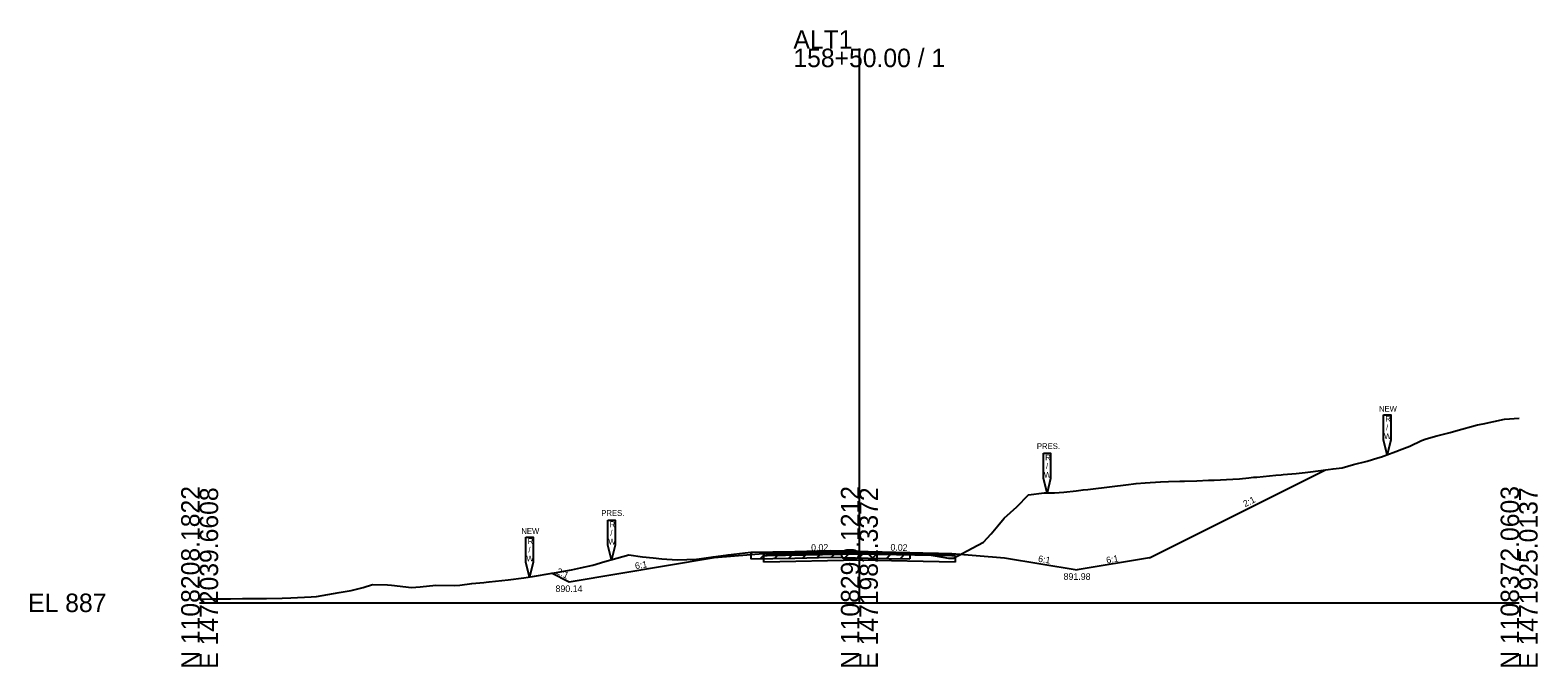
# Model space of a CAD drawing. Extents: x -26 to 2203, y -10 to 19568.
# Drawn here: x 974.3 to 1202.8, y 490.3 to 586.7 of the extents above; entities that cross this region are included whole.
import ezdxf

# ---------------------------------------------------------------- set-up
doc = ezdxf.new("R2010")
doc.units = 0
for name, color, linetype in [('RD_GPK_XS_Cell', 7, 'Continuous'), ('RD_XS_Base', 7, 'Continuous'), ('RD_XS_ExGround', 7, 'Continuous'), ('RD_XS_ExPaveRet', 7, 'Continuous'), ('RD_XS_ExRW', 7, 'Continuous'), ('RD_XS_Greenside', 7, 'Continuous'), ('RD_XS_NewRW', 7, 'Continuous'), ('RD_XS_Pave', 7, 'Continuous'), ('RD_XS_TieSlope', 7, 'Continuous'), ('RD_XS_TX_Slope', 7, 'Continuous')]:
    doc.layers.add(name, color=color, linetype=linetype)

msp = doc.modelspace()

# ---------------------------------------------------------------- linework, layer by layer
at = {"layer": 'RD_GPK_XS_Cell'}
for p, q in [((1100, 500), (1100, 583.93)), ((1000, 500), (1100, 500)), ((1100, 500), (1200, 500))]:
    msp.add_line(p, q, dxfattribs=at)
at = {"layer": 'RD_XS_Base'}
for points in [[(1085.5, 507.15), (1086, 507.16), (1100, 507.44), (1114, 507.16), (1114.5, 507.15)], [(1085.5, 506.15), (1085.5, 507.15)], [(1114.5, 506.15), (1100, 506.44), (1085.5, 506.15)], [(1114.5, 507.15), (1114.5, 506.15)]]:
    msp.add_lwpolyline(points, dxfattribs=at)
at = {"layer": 'RD_XS_ExGround'}
msp.add_lwpolyline([(1000, 500.54), (1002.02, 500.59), (1002.83, 500.6), (1004.65, 500.6), (1006.49, 500.63), (1007.26, 500.63), (1010.15, 500.66), (1012.49, 500.72), (1013.81, 500.76), (1016.89, 500.9), (1017.73, 500.97), (1021.13, 501.54), (1022.96, 501.85), (1024.8, 502.31), (1026.19, 502.75), (1028.46, 502.71), (1029.08, 502.65), (1032.12, 502.33), (1033.43, 502.43), (1035.78, 502.65), (1038.66, 502.64), (1039.44, 502.67), (1041.27, 502.92), (1043.1, 503.09), (1043.43, 503.13), (1043.89, 503.2), (1046.76, 503.49), (1049.13, 503.78), (1050.43, 504.01), (1053.45, 504.51), (1054.36, 504.66), (1056.35, 505), (1057.75, 505.28), (1059.59, 505.71), (1061.41, 506.25), (1065.07, 507.26), (1067.12, 506.99), (1068.73, 506.82), (1070.06, 506.67), (1072.39, 506.49), (1075.29, 506.63), (1076.05, 506.7), (1077.83, 506.96), (1080.09, 507.27), (1083.57, 507.65), (1090.21, 507.78), (1095.64, 507.9), (1100, 507.8), (1101.35, 507.77), (1107.66, 507.64), (1109.78, 507.42), (1110.3, 507.33), (1113.51, 506.75), (1114.25, 506.75), (1117.11, 508.28), (1118.82, 509.21), (1119.99, 510.44), (1120.98, 511.67), (1121.97, 512.84), (1123.85, 514.56), (1125.63, 516.36), (1128.02, 516.64), (1129.6, 516.67), (1130.97, 516.75), (1132.86, 516.96), (1133.9, 517.1), (1134.63, 517.16), (1138.3, 517.61), (1140.37, 517.85), (1141.96, 518.07), (1143.33, 518.19), (1145.62, 518.31), (1146.83, 518.38), (1148.56, 518.43), (1149.28, 518.45), (1151.14, 518.5), (1152.94, 518.56), (1153.8, 518.6), (1156.6, 518.73), (1157.6, 518.8), (1159.03, 518.94), (1159.75, 519.01), (1160.26, 519.04), (1163.14, 519.31), (1163.92, 519.38), (1164.26, 519.41), (1166.22, 519.6), (1167.59, 519.74), (1168.37, 519.82), (1169.56, 519.98), (1171.83, 520.31), (1173.16, 520.47), (1174.9, 520.94), (1176.99, 521.47), (1178.57, 521.94), (1179.14, 522.12), (1179.96, 522.43), (1181.3, 522.91), (1182.23, 523.27), (1183.45, 523.73), (1185.2, 524.57), (1185.89, 524.84), (1187.51, 525.27), (1189.55, 525.79), (1190.42, 526.03), (1193.67, 526.94), (1194.53, 527.09), (1197.81, 527.8), (1200, 527.98)], dxfattribs=at)
at = {"layer": 'RD_XS_ExPaveRet'}
for p, q in [((1083.57, 507.41), (1083.81, 507.66)), ((1083.57, 507.65), (1083.57, 506.65)), ((1084.96, 506.68), (1085.98, 507.7)), ((1087.12, 506.72), (1088.14, 507.74)), ((1089.29, 506.76), (1090.31, 507.79)), ((1091.45, 506.81), (1092.48, 507.83)), ((1093.62, 506.86), (1094.64, 507.88)), ((1095.78, 506.9), (1096.76, 507.87)), ((1097.86, 506.85), (1098.84, 507.83)), ((1099.93, 506.8), (1100.91, 507.78)), ((1102.01, 506.76), (1102.99, 507.74)), ((1104.09, 506.71), (1105.07, 507.69)), ((1106.17, 506.67), (1107.15, 507.65)), ((1107.66, 507.64), (1107.66, 506.64))]:
    msp.add_line(p, q, dxfattribs=at)
msp.add_lwpolyline([(1083.57, 506.65), (1090.23, 506.78), (1095.64, 506.9), (1101.33, 506.77), (1107.66, 506.64)], dxfattribs=at)
at = {"layer": 'RD_XS_ExRW'}
for points in [[(1127.9, 522.66), (1128.99, 522.66), (1128.99, 518.83), (1128.44, 516.65), (1127.9, 518.83)], [(1061.87, 512.54), (1062.96, 512.54), (1062.96, 508.71), (1062.42, 506.53), (1061.87, 508.71)]]:
    msp.add_lwpolyline(points, close=True, dxfattribs=at)
at = {"layer": 'RD_XS_Greenside'}
for points in [[(1086, 507.48), (1078, 506.81)], [(1114, 507.48), (1122, 506.81)], [(1078, 506.81), (1056, 503.14)], [(1122, 506.81), (1133, 504.98)], [(1144, 506.81), (1133, 504.98)]]:
    msp.add_lwpolyline(points, dxfattribs=at)
at = {"layer": 'RD_XS_NewRW'}
for points in [[(1179.45, 528.47), (1180.55, 528.47), (1180.55, 524.64), (1180, 522.45), (1179.45, 524.64)], [(1049.45, 509.95), (1050.55, 509.95), (1050.55, 506.12), (1050, 503.94), (1049.45, 506.12)]]:
    msp.add_lwpolyline(points, close=True, dxfattribs=at)
at = {"layer": 'RD_XS_Pave'}
for points in [[(1086, 507.48), (1088, 507.52), (1100, 507.76), (1112, 507.52), (1114, 507.48)], [(1086, 507.32), (1100, 507.6), (1114, 507.32)], [(1114, 507.32), (1100, 507.6), (1086, 507.32)], [(1086, 507.32), (1086, 507.48)], [(1114, 507.16), (1100, 507.44), (1086, 507.16)], [(1114, 507.48), (1114, 507.32)], [(1086, 507.16), (1086, 507.32)], [(1114, 507.32), (1114, 507.16)]]:
    msp.add_lwpolyline(points, dxfattribs=at)
at = {"layer": 'RD_XS_TieSlope'}
for points in [[(1144, 506.81), (1170.64, 520.13)], [(1056, 503.14), (1053.31, 504.49)]]:
    msp.add_lwpolyline(points, dxfattribs=at)

# ---------------------------------------------------------------- texts
at = {"layer": 'RD_GPK_XS_Cell'}
for s, p in [('ALT1', (1090, 583.93)), ('158+50.00 / 1', (1090, 581.13)), ('EL 887', (974, 498.6))]:
    msp.add_text(s, height=2.8, dxfattribs=at).set_placement(p)
for s, p in [('N 1108208.1822', (1000, 490)), ('E 1472039.6608', (1002.8, 490)), ('N 1108290.1212', (1100, 490)), ('E 1471982.3372', (1102.8, 490)), ('N 1108372.0603', (1200, 490)), ('E 1471925.0137', (1202.8, 490))]:
    msp.add_text(s, height=2.8, rotation=90, dxfattribs=at).set_placement(p)
at = {"layer": 'RD_XS_ExRW'}
for s, p in [('PRES.', (1126.9, 523.29)), ('R', (1128.16, 521.57)), ('/', (1128.28, 520.26)), ('W', (1127.97, 518.95)), ('PRES.', (1060.87, 513.17)), ('R', (1062.13, 511.45)), ('W', (1061.95, 508.83)), ('/', (1062.25, 510.14))]:
    msp.add_text(s, height=0.875, dxfattribs=at).set_placement(p)
at = {"layer": 'RD_XS_NewRW'}
for s, p in [('NEW', (1178.75, 528.95)), ('R', (1179.71, 527.43)), ('W', (1179.53, 524.8)), ('/', (1179.83, 526.12)), ('NEW', (1048.75, 510.44)), ('R', (1049.71, 508.91)), ('/', (1049.83, 507.6)), ('W', (1049.53, 506.29))]:
    msp.add_text(s, height=0.875, dxfattribs=at).set_placement(p)
at = {"layer": 'RD_XS_TX_Slope'}
for s, rotation, p in [('2:1', 26.5651, (1158.47, 514.47)), ('0.02', 1.1458, (1092.69, 507.86)), ('0.02', 358.8542, (1104.7, 507.91)), ('2:1', 333.4349, (1053.97, 504.44)), ('6:1', 9.4642, (1066.07, 505.08)), ('6:1', 350.5358, (1127.04, 506.23)), ('6:1', 10.416, (1137.51, 505.94))]:
    msp.add_text(s, height=1, rotation=rotation, dxfattribs=at).set_placement(p)
for s, p in [('891.98', (1130.95, 503.48)), ('890.14', (1053.94, 501.64))]:
    msp.add_text(s, height=1, dxfattribs=at).set_placement(p)

doc.saveas('drawing.dxf')
